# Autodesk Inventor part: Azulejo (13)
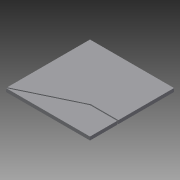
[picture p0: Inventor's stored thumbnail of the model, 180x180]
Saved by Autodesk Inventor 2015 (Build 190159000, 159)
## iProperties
Created: 2015-04
Part Number: Azulejo (13)
Material: Genérico
Document SubType Name: Modeling
Designer: Felipe
Density: 1 g/cm^3
Appearance: Padrão
Author: Felipe
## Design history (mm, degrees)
sketch "Sketch1"
  geometry: L1 (-1510, -7490)-(-1510, -6010); L2 (992.445, 7510)-(992.445, 8990); L3 (1012.445, 7510)-(1012.445, 8990); L4 (-3010, -1490)-(-3010, -10); L5 (-1510, 7490)-(-2990, 7490); L6 (-2990, 10)-(-1510, 10); L7 (-1510, -10)-(-2990, -10); L8 (-1510, -1490)-(-1510, -10); L9 (-3010, 7490)-(-4490, 7490); L10 (-3010, 5990)-(-4490, 5990); L11 (-10, 9010)-(-10, 10490); L12 (-10, 7510)-(-10, 8990); L13 (-10, 7490)-(-1490, 7490); L14 (-1490, 6010)-(-10, 6010); L15 (-10, 5990)-(-1490, 5990); L16 (-1490, -10)-(-1490, -1490); L17 (-1490, -1490)-(-10, -1490); L18 (-10, -1510)-(-1490, -1510); L19 (-10, -2990)-(-10, -1510); L20 (-10, -5990)-(-10, -4510); L21 (-1490, -7490)-(-10, -7490); L22 (10, 8990)-(10, 7510); L23 (1490, 7510)-(1490, 8990); L24 (10, 6010)-(1490, 6010); L25 (1490, 6010)-(1490, 7490); L26 (1490, 5990)-(10, 5990); L27 (4490, -6010)-(3010, -6010); L28 (10, -1510)-(10, -2990); L29 (10, -3010)-(10, -4490); L30 (10, -4510)-(10, -5990); L31 (10, -5990)-(1490, -5990); L32 (1490, -6010)-(10, -6010); L33 (10, -7490)-(1490, -7490); L34 (2990, 9010)-(2990, 10490); L35 (1510, 8990)-(1510, 7510); L36 (1510, 7510)-(2990, 7510); L37 (2990, 7490)-(1510, 7490); L38 (1510, 7490)-(1510, 6010); L39 (1510, -5990)-(2990, -5990); L40 (2990, -6010)-(1510, -6010); L41 (1510, -7490)-(2990, -7490); L42 (3010, 10490)-(3010, 9010); L43 (3010, 9010)-(4490, 9010); L44 (4490, 8990)-(3010, 8990); L45 (4490, 7490)-(3010, 7490); L46 (4490, 1510)-(4490, 2990); L47 (4490, 10)-(4490, 1490); L48 (4490, -1490)-(4490, -10); L49 (4490, -2990)-(4490, -1510); L50 (3010, -5990)-(4490, -5990); L51 (3010, -7490)-(4490, -7490); L52 (4510, 9010)-(5990, 9010); L53 (5990, 8990)-(4510, 8990); L54 (4510, 7510)-(5990, 7510); L55 (5990, 7490)-(4510, 7490); L56 (4510, 3010)-(5990, 3010); L57 (5990, 2990)-(4510, 2990); L58 (4510, 2990)-(4510, 1510); L59 (4510, 1510)-(5990, 1510); L60 (5990, 1510)-(5990, 1740.185); L61 (5990, 1760.2)-(5990, 2259.8); L62 (5990, 2279.815)-(5990, 2990); L63 (5990, 1490)-(4510, 1490); L64 (4510, 1490)-(4510, 10)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; A1 r 250 centre (6000, 2010) between (5990, 2259.8) and (5990, 1760.2); A2 r 250 centre (6000, 2010) between (6010, 1760.2) and (6010, 2259.8); A3 r 270 centre (6000, 2010) between (5990, 2279.815) and (5990, 1740.185); A4 r 270 centre (6000, 2010) between (6010, 1740.185) and (6010, 2279.815); A5 r 3010.017 centre (0, 0) between (-1490, -2615.358) and (-346.554, -2990); A6 r 2990.017 centre (0, 0) between (-1490, -2592.316) and (-10, -2990); A7 r 3010.017 centre (0, 0) between (-2603.863, -1510) and (-1510, -2603.863); A8 r 2990.017 centre (0, 0) between (-2580.717, -1510) and (-1510, -2580.717); A9 r 3010.017 centre (0, 0) between (-2990, -346.554) and (-2615.358, -1490); A10 r 2990.017 centre (0, 0) between (-2990, -10) and (-2592.316, -1490); A11 r 2131.367 centre (7500, -1500) between (7490, 631.344) and (6010, 24.017); A12 r 2131.367 centre (7500, -1500) between (5975.983, -10) and (5368.656, -1490); A13 r 2131.367 centre (7500, -1500) between (5368.656, -1510) and (5975.983, -2990); A14 r 2131.367 centre (7500, -1500) between (6010, -3024.017) and (7190, -3608.703); A15 r 1831.367 centre (7500, -1500) between (7490.321, 331.342) and (6463.753, 10); A16 r 1831.367 centre (7500, -1500) between (6435.196, -10) and (6010, -435.196); A17 r 1831.367 centre (7500, -1500) between (5990, -463.753) and (5668.66, -1490); A18 r 1831.367 centre (7500, -1500) between (5668.66, -1510) and (5990, -2536.247); A19 r 1831.367 centre (7500, -1500) between (6010, -2564.804) and (6435.196, -2990); A20 r 1831.367 centre (7500, -1500) between (6463.753, -3010) and (7490, -3331.34); A21 r 2111.367 centre (7500, -1500) between (7490.047, 611.344) and (6024.272, 10); A22 r 2111.367 centre (7500, -1500) between (5990, -24.272) and (5388.656, -1490); A23 r 2111.367 centre (7500, -1500) between (5388.656, -1510) and (5990, -2975.728); A24 r 2111.367 centre (7500, -1500) between (6024.272, -3010) and (7210, -3591.357); A25 r 1811.367 centre (7500, -1500) between (7490.374, 311.342) and (6499.524, 10); A26 r 1811.367 centre (7500, -1500) between (6469.975, -10) and (6010, -469.975); A27 r 1811.367 centre (7500, -1500) between (5990, -499.524) and (5688.66, -1490); A28 r 1811.367 centre (7500, -1500) between (5688.66, -1510) and (5990, -2500.476); A29 r 1811.367 centre (7500, -1500) between (6010, -2530.025) and (6469.975, -2990); A30 r 1811.367 centre (7500, -1500) between (6499.524, -3010) and (7490, -3311.34); A31 r 449.871 centre (7499.449, -4060.672) between (7510, -4510.419) and (7521.546, -4510); 3 further points
  constraints: 1062 end point, 64 point on circle, 31 centre point, 13 point on line, 1 perpendicular, 1 other
extrude "Extrusion1" new body sketch "Sketch1" distance "d0" = 60; taper "d1" = 0 deg
extrude "Extrusion2" new body sketch "Sketch1" distance "d2" = 60; taper "d3" = 0 deg
body "Solid1"
body "Solid2"
